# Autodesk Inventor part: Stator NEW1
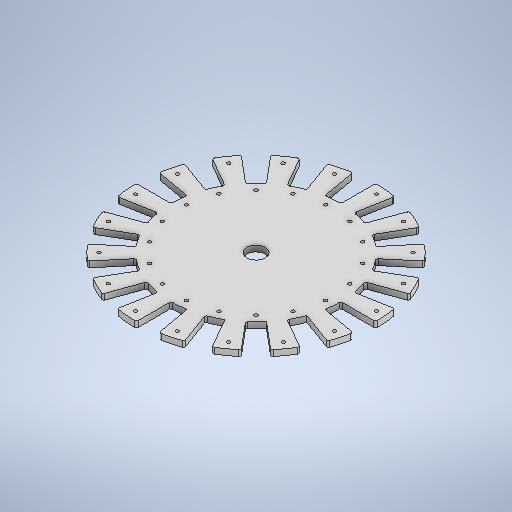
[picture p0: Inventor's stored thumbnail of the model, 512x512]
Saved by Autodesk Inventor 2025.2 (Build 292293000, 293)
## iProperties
Created: 2025-05
Part Number: Stator NEW1
Material: Generic
Document SubType Name: Modeling
Designer: bensa
Density: 1 g/cm^3
Appearance: Default
Author: bensa
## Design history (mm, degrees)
sketch "Sketch1"
  geometry: C1 r 141.65 at (0, 0); 1 further point
  constraints: 1 centre point, 1 coincident
  dimensions: "d0" = 283.3 diameter of C1
sketch "Sketch2"
  geometry: C1 r 145.5 at (0, 0); 1 further point
  constraints: 1 centre point, 1 coincident
  dimensions: "d1" = 291 diameter of C1
extrude "Extrusion1" new body sketch "Sketch1" distance "d2" = 19; taper "d3" = 0 deg
extrude "Extrusion2" join sketch "Sketch2" distance "d4" = 1; taper "d5" = 0 deg
sketch "Sketch3" dims "d23" = 201.3
  geometry: L1 (-141.65, 0)-(141.65, 0); L2 (0, 141.65)-(0, -141.65); L3 (-139.498, -24.597)-(139.498, 24.597); L4 (-133.107, -48.447)-(133.107, 48.447); L5 (-122.672, -70.825)-(122.672, 70.825); L6 (-108.51, -91.051)-(108.51, 91.051); L7 (-91.051, -108.51)-(91.051, 108.51); L8 (-70.825, -122.672)-(70.825, 122.672); L9 (-48.447, -133.107)-(48.447, 133.107); L10 (-24.597, -139.498)-(24.597, 139.498); L11 (24.597, -139.498)-(-24.597, 139.498); L12 (48.447, -133.107)-(-48.447, 133.107); L13 (70.825, -122.672)-(-70.825, 122.672); L14 (91.051, -108.51)-(-91.051, 108.51); L15 (122.672, -70.825)-(-122.672, 70.825); L16 (133.107, -48.447)-(-133.107, 48.447); L17 (139.498, -24.597)-(-139.498, 24.597); L18 (108.51, -91.051)-(-108.51, 91.051); C1 r 145.5 at (0, 0) reference; 66 further points
  constraints: 36 end point, 18 midpoint, 4 perpendicular, 1 coincident, 1 horizontal, 11 other
extrude "Extrusion3" cut sketch "Sketch3" distance "d24" = 7; taper "d25" = 0 deg
fillet "Fillet1" dims "d26" = 2
fillet "Fillet2" dims "d27" = 2
fillet "Fillet3" dims "d28" = 2
fillet "Fillet4" dims "d29" = 2
sketch "Sketch4"
  geometry: L1 (-82.448, -57.73)-(-74.256, -51.995); L2 (-97.22, -26.05)-(-87.561, -23.462); L3 (-57.73, -82.448)-(-51.995, -74.256); L4 (-26.05, -97.22)-(-23.462, -87.561); L5 (-100.217, 8.768)-(-90.255, 7.896); L6 (-91.22, 42.537)-(-82.157, 38.31); L7 (-71.17, 71.17)-(-64.099, 64.099); L8 (-42.537, 91.22)-(-38.31, 82.157); L9 (-8.772, 100.267)-(-7.901, 90.305); L10 (26.05, 97.22)-(23.462, 87.561); L11 (57.73, 82.448)-(51.995, 74.256); L12 (82.448, 57.73)-(74.256, 51.995); L13 (97.22, 26.05)-(87.561, 23.462); L14 (100.217, -8.768)-(90.255, -7.896); L15 (91.22, -42.537)-(82.157, -38.31); L16 (71.17, -71.17)-(64.099, -64.099); L17 (42.537, -91.22)-(38.31, -82.157); L18 (8.772, -100.267)-(7.901, -90.305); A1 r 100.65 centre (0, 0) between (88.129, -48.617) and (94.58, -34.424) reference; A2 r 100.65 centre (0, 0) between (-99.443, 15.543) and (-100.631, 1.961) reference; A3 r 100.65 centre (0, 0) between (-99.443, 15.543) and (-100.631, 1.961) reference; A4 r 100.65 centre (0, 0) between (-99.443, 15.543) and (-100.631, 1.961) reference; A5 r 100.65 centre (0, 0) between (32.575, 95.233) and (19.406, 98.762) reference; A6 r 100.65 centre (0, 0) between (63.182, 78.348) and (52.014, 86.168) reference; 8 further points
  constraints: 36 end point
hole "Hole1" sketch "Sketch4" diameter "d66" = 4; stored, may be unused: countersink angle "d70" = 90 deg, drill point angle "d72" = 118 deg; dims "d67" = 6, "d68" = 4, "d69" = 2, "d71" = 8
sketch "Sketch5"
  geometry: L1 (-100.162, -100.162)-(-93.091, -93.091); L2 (-128.333, -59.843)-(-119.27, -55.617); L3 (-59.864, -128.378)-(-55.638, -119.315); L4 (-12.346, -141.111)-(-11.474, -131.149); L5 (36.662, -136.823)-(34.074, -127.164); L6 (81.247, -116.033)-(75.511, -107.841); L7 (116.033, -81.247)-(107.841, -75.511); L8 (136.823, -36.662)-(127.164, -34.074); L9 (141.111, 12.346)-(131.149, 11.474); L10 (128.333, 59.843)-(119.27, 55.617); L11 (100.162, 100.162)-(93.091, 93.091); L12 (59.864, 128.378)-(55.638, 119.315); L13 (12.346, 141.111)-(11.474, 131.149); L14 (-36.662, 136.823)-(-34.074, 127.164); L15 (-141.111, -12.346)-(-131.149, -11.474); L16 (-136.823, 36.662)-(-127.164, 34.074); L17 (-116.033, 81.247)-(-107.841, 75.511); L18 (-81.247, 116.033)-(-75.511, 107.841); C1 r 145.5 at (0, 0) reference; A1 r 141.65 centre (0, 0) between (-133.788, 46.536) and (-139.131, 26.593) reference; A2 r 141.65 centre (0, 0) between (-72.575, 121.646) and (-89.487, 109.803) reference; A3 r 141.65 centre (0, 0) between (-26.593, 139.131) and (-46.536, 133.788) reference; A4 r 141.65 centre (0, 0) between (22.597, 139.836) and (2.029, 141.635) reference; A5 r 141.65 centre (0, 0) between (132.4, 50.348) and (123.674, 69.061) reference; 1 further point
  constraints: 36 end point, 1 point on circle
hole "Hole2" sketch "Sketch5" diameter "d109" = 4; stored, may be unused: countersink angle "d113" = 90 deg, drill point angle "d115" = 118 deg; dims "d110" = 6, "d111" = 4, "d112" = 2, "d114" = 8
sketch "Sketch6"
  geometry: 1 further point
hole "Hole3" sketch "Sketch6" at (0, 0) diameter "d116" = 22; stored, may be unused: countersink angle "d120" = 90 deg, drill point angle "d122" = 118 deg; dims "d117" = 6, "d118" = 4, "d119" = 2, "d121" = 8
delete_face "Delete Face1"
sketch "Sketch8"
  geometry: C1 r 141.65 at (0, 0); 1 further point
  constraints: 1 centre point, 1 coincident
extrude "Extrusion4" cut sketch "Sketch8" distance "d124" = 13; taper "d125" = 0 deg
body "Solid1"
